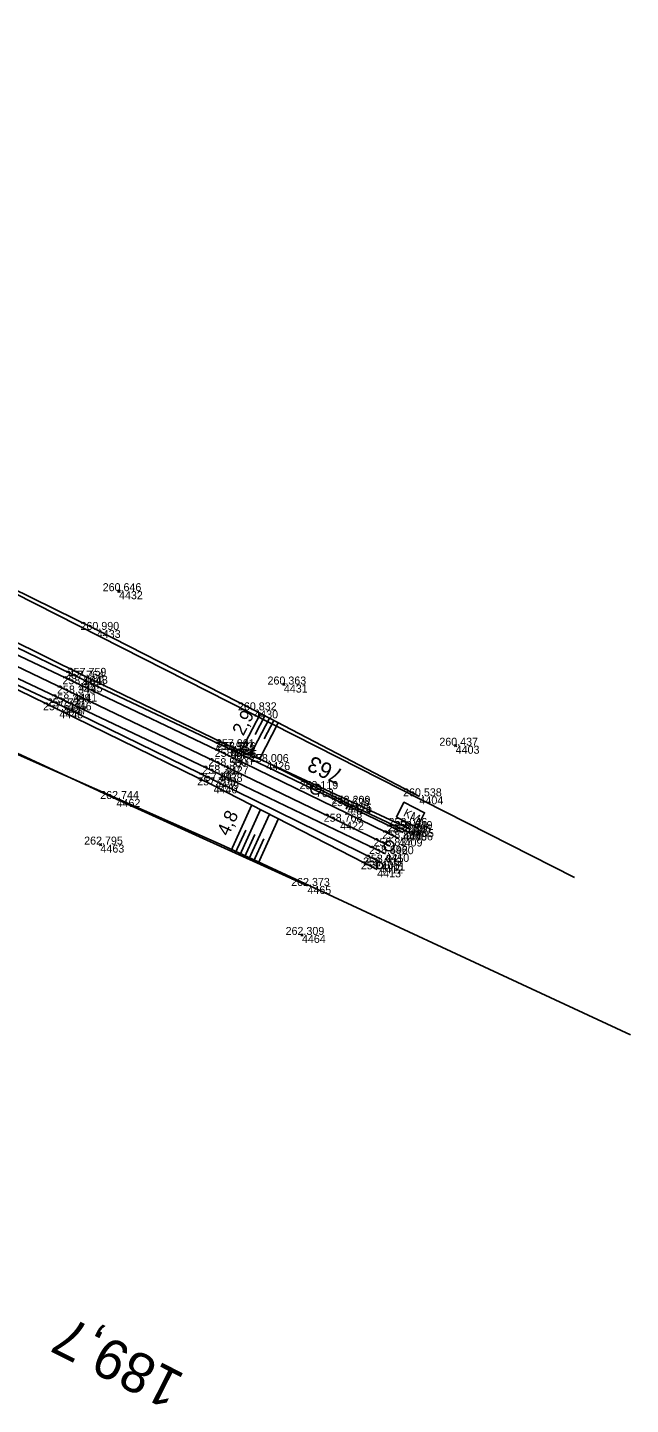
# Model space of a CAD drawing. Extents: x -809970 to -809480, y -1011362 to -1010672.
# Drawn here: x -809570.4 to -809480, y -1011362.4 to -1011155.9 of the extents above; entities that cross this region are included whole.
import ezdxf

# ---------------------------------------------------------------- set-up
doc = ezdxf.new("R2010")
doc.units = 0
for name, color, linetype in [('Vrstva 1', 7, 'Continuous'), ('Vrstva 4', 7, 'Continuous'), ('Vrstva 48', 7, 'Continuous'), ('Vrstva 49', 7, 'Continuous'), ('Vrstva 53', 7, 'Continuous'), ('Vrstva 60', 7, 'Continuous'), ('Vrstva 61', 7, 'Continuous'), ('Vrstva 63', 7, 'Continuous'), ('Vrstva 7', 7, 'Continuous')]:
    doc.layers.add(name, color=color, linetype=linetype)

msp = doc.modelspace()

# ---------------------------------------------------------------- linework, layer by layer
at = {"layer": 'Vrstva 1'}
msp.add_lwpolyline([(-809516.05, -1011278.71), (-809523.51, -1011275.04), (-809540.81, -1011266.71), (-809563.53, -1011255.81), (-809585.84, -1011245.11), (-809604.95, -1011235.93), (-809607.6, -1011234.66), (-809621.68, -1011227.86)], dxfattribs=at)
at = {"layer": 'Vrstva 4'}
for points in [[(-809514.07, -1011276.67), (-809539.83, -1011264.26), (-809562.29, -1011253.6), (-809585.06, -1011242.59), (-809604.03, -1011233.74), (-809622.75, -1011224.34), (-809635.98, -1011217.78), (-809658.04, -1011205.96), (-809678.21, -1011194.44), (-809694.3, -1011183.84), (-809703.86, -1011176.66), (-809724.9, -1011159.78), (-809744.11, -1011141.6), (-809762.15, -1011122.16), (-809774.57, -1011106.33), (-809789.63, -1011085.97), (-809801.28, -1011067.08), (-809811.54, -1011048.02), (-809817.16, -1011036.69), (-809823.08, -1011022.98)], [(-809514.73, -1011277.55), (-809539.87, -1011265.31), (-809562.72, -1011254.42), (-809585.31, -1011243.69), (-809604.51, -1011234.26), (-809623.3, -1011225.16), (-809636.52, -1011218.94), (-809659.57, -1011206.8), (-809678.11, -1011195.78), (-809694.14, -1011185.08), (-809704.56, -1011177.6), (-809725.72, -1011160.53), (-809745.22, -1011142.43), (-809763.07, -1011123.23), (-809775.62, -1011107.42), (-809790.76, -1011086.7), (-809802.43, -1011068.09), (-809812.88, -1011048.59), (-809818.37, -1011037.45), (-809824.5, -1011023.86)], [(-809517.34, -1011281.17), (-809542.25, -1011268.91), (-809565.05, -1011257.74), (-809585.85, -1011248.03), (-809606.19, -1011237.96), (-809624.44, -1011229.46), (-809639.03, -1011221.78), (-809662.37, -1011209.59), (-809679.75, -1011199.24), (-809695.35, -1011189.16), (-809706.37, -1011181.63), (-809728.71, -1011163.52), (-809748.04, -1011145.82), (-809766.46, -1011126.18), (-809779.35, -1011110.29), (-809779.4, -1011110.26), (-809794.33, -1011089.31), (-809806.51, -1011070.34), (-809817.46, -1011050.77), (-809822.78, -1011039.81), (-809827.65, -1011029.26)], [(-809516.72, -1011279.86), (-809541.72, -1011267.84), (-809564.36, -1011257.13), (-809585.64, -1011247.05), (-809605.96, -1011237.21), (-809624.35, -1011228.4), (-809638.66, -1011221.38), (-809661.97, -1011208.93), (-809679.17, -1011198.73), (-809694.94, -1011188.71), (-809705.67, -1011180.87), (-809727.9, -1011162.91), (-809747.29, -1011144.85), (-809765.46, -1011125.12), (-809778.44, -1011109.55), (-809793.36, -1011088.57), (-809805.27, -1011069.6), (-809816.07, -1011050.21), (-809821.49, -1011039.16), (-809826.21, -1011028.82)]]:
    msp.add_lwpolyline(points, dxfattribs=at)
at = {"layer": 'Vrstva 48'}
for p, q in [((-809535.46, -1011258.81), (-809538.4, -1011264.45)), ((-809534.13, -1011259.51), (-809537.02, -1011265.04)), ((-809534.8, -1011259.16), (-809536.25, -1011261.95)), ((-809532.8, -1011260.2), (-809535.63, -1011265.64)), ((-809533.47, -1011259.85), (-809534.9, -1011262.59)), ((-809539.93, -1011279.43), (-809536.78, -1011272.51)), ((-809538.56, -1011280.05), (-809535.44, -1011273.2)), ((-809537.2, -1011280.67), (-809534.11, -1011273.88)), ((-809535.83, -1011281.29), (-809532.77, -1011274.57)), ((-809539.24, -1011279.74), (-809537.68, -1011276.3)), ((-809537.88, -1011280.36), (-809536.33, -1011276.95)), ((-809536.51, -1011280.98), (-809534.97, -1011277.6))]:
    msp.add_line(p, q, dxfattribs=at)
at = {"layer": 'Vrstva 49'}
for p, q in [((-809556.85, -1011240.28), (-809556.5, -1011240.64)), ((-809556.85, -1011240.64), (-809556.5, -1011240.28)), ((-809532.13, -1011254.28), (-809531.77, -1011254.63)), ((-809532.13, -1011254.63), (-809531.77, -1011254.28)), ((-809506.36, -1011263.46), (-809506, -1011263.82)), ((-809506.36, -1011263.82), (-809506, -1011263.46)), ((-809559.63, -1011278.29), (-809559.28, -1011278.64)), ((-809559.63, -1011278.64), (-809559.28, -1011278.29)), ((-809529.41, -1011291.84), (-809529.06, -1011292.19)), ((-809529.41, -1011292.19), (-809529.06, -1011291.84))]:
    msp.add_line(p, q, dxfattribs=at)
for points in [[(-809511.61, -1011271.23), (-809536.39, -1011258.33), (-809560.01, -1011246.27), (-809576.21, -1011238.32), (-809612.21, -1011219.9), (-809615.12, -1011217.12), (-809615.79, -1011215.73), (-809619.54, -1011223.55), (-809624.01, -1011221.32), (-809620.33, -1011213.39), (-809626.47, -1011211.63), (-809636.4, -1011208.19), (-809641.71, -1011205.47), (-809669.15, -1011190.8), (-809699.73, -1011169.4), (-809726.54, -1011146.85), (-809748.5, -1011124.91), (-809769.57, -1011100.55), (-809784.98, -1011078.51), (-809794.37, -1011063.91), (-809798.01, -1011059.09), (-809806.77, -1011045.25), (-809814.25, -1011034.46), (-809820.96, -1011021.87)], [(-809517.95, -1011282.18), (-809542.49, -1011269.58), (-809565.63, -1011258.32), (-809585.98, -1011248.4), (-809606.44, -1011238.24), (-809621.62, -1011231.05), (-809624.45, -1011230.4), (-809627.73, -1011228.86), (-809639.59, -1011222.81), (-809662.84, -1011211.14), (-809680.58, -1011200.68), (-809695.92, -1011190.37), (-809707.33, -1011182.3), (-809729.57, -1011164.32), (-809748.84, -1011146.41), (-809766.98, -1011126.93), (-809779.99, -1011110.78), (-809794.75, -1011089.67), (-809807.08, -1011070.6), (-809818.27, -1011051.22), (-809824.25, -1011040.29), (-809829.11, -1011030.23)], [(-809513.01, -1011276.14), (-809534.58, -1011266.09), (-809539.77, -1011263.86), (-809561.92, -1011253.16), (-809584.64, -1011241.91), (-809603.49, -1011232.88), (-809619.73, -1011225.04), (-809620.87, -1011223.99), (-809623.85, -1011222.57), (-809625.32, -1011222.49), (-809635.81, -1011217.56), (-809657.91, -1011205.7), (-809678.34, -1011193.87), (-809696.27, -1011181.61), (-809696.31, -1011181.59), (-809703.94, -1011175.69), (-809724.27, -1011159.21)], [(-809528.41, -1011284.67), (-809557.05, -1011271.63), (-809578.05, -1011261.94), (-809594.42, -1011254.32), (-809626.26, -1011240.21), (-809627.58, -1011240.01), (-809623.67, -1011231.94), (-809628.13, -1011229.78), (-809632.16, -1011237.96), (-809631.7, -1011238.19), (-809633.92, -1011240.11), (-809638.94, -1011239.66), (-809644.87, -1011236.23), (-809666.21, -1011225), (-809686, -1011209.54), (-809702.86, -1011197.5), (-809722.79, -1011182.74)], [(-809513.17, -1011276.63), (-809522.32, -1011272.35), (-809534.58, -1011266.09)]]:
    msp.add_lwpolyline(points, dxfattribs=at)
at = {"layer": 'Vrstva 53'}
for points in [[(-809817.83, -1011024.91), (-809805.06, -1011048.21), (-809777.13, -1011090.84), (-809773.31, -1011095.41), (-809752.3, -1011120.38), (-809722.41, -1011150.52), (-809685.06, -1011180.11), (-809638.61, -1011207.44), (-809624.45, -1011211.08), (-809620, -1011212.86), (-809615.56, -1011215.28), (-809614.76, -1011215.85), (-809598.39, -1011227.55), (-809488.36, -1011283.38)], [(-809479.96, -1011306.98), (-809541.53, -1011278.39), (-809624.88, -1011241.51), (-809627.72, -1011240.25), (-809632.39, -1011238.49), (-809632.72, -1011238.43), (-809644.97, -1011236.14), (-809685.42, -1011208.04), (-809719.22, -1011184.3), (-809751.99, -1011157.11), (-809779.01, -1011125.97), (-809796.54, -1011101.19), (-809810.89, -1011076.81), (-809836.26, -1011028.53)]]:
    msp.add_lwpolyline(points, dxfattribs=at)
at = {"layer": 'Vrstva 60'}
for p, q in [((-809556.68, -1011240.46), (-809556.68, -1011240.46)), ((-809560.01, -1011246.27), (-809560.01, -1011246.27)), ((-809562.72, -1011254.42), (-809562.72, -1011254.42)), ((-809562.29, -1011253.6), (-809562.29, -1011253.6)), ((-809561.92, -1011253.16), (-809561.92, -1011253.16)), ((-809531.95, -1011254.46), (-809531.95, -1011254.46)), ((-809563.53, -1011255.81), (-809563.53, -1011255.81)), ((-809565.63, -1011258.32), (-809565.63, -1011258.32)), ((-809565.05, -1011257.74), (-809565.05, -1011257.74)), ((-809564.36, -1011257.13), (-809564.36, -1011257.13)), ((-809536.39, -1011258.33), (-809536.39, -1011258.33)), ((-809539.83, -1011264.26), (-809539.83, -1011264.26)), ((-809539.77, -1011263.86), (-809539.77, -1011263.86)), ((-809539.53, -1011264.29), (-809539.53, -1011264.29)), ((-809506.18, -1011263.64), (-809506.18, -1011263.64)), ((-809540.81, -1011266.71), (-809540.81, -1011266.71)), ((-809539.87, -1011265.31), (-809539.87, -1011265.31)), ((-809534.58, -1011266.09), (-809534.58, -1011266.09)), ((-809542.25, -1011268.91), (-809542.25, -1011268.91)), ((-809541.72, -1011267.84), (-809541.72, -1011267.84)), ((-809542.49, -1011269.58), (-809542.49, -1011269.58)), ((-809527.15, -1011270.15), (-809527.15, -1011270.15)), ((-809557.05, -1011271.63), (-809557.05, -1011271.63)), ((-809522.41, -1011272.7), (-809522.41, -1011272.7)), ((-809522.32, -1011272.35), (-809522.32, -1011272.35)), ((-809511.61, -1011271.23), (-809511.61, -1011271.23)), ((-809523.51, -1011275.04), (-809523.51, -1011275.04)), ((-809514.07, -1011276.67), (-809514.07, -1011276.67)), ((-809513.79, -1011275.68), (-809513.79, -1011275.68)), ((-809513.17, -1011276.63), (-809513.17, -1011276.63)), ((-809513.01, -1011276.14), (-809513.01, -1011276.14)), ((-809559.46, -1011278.47), (-809559.46, -1011278.47)), ((-809516.05, -1011278.71), (-809516.05, -1011278.71)), ((-809514.73, -1011277.55), (-809514.73, -1011277.55)), ((-809517.34, -1011281.17), (-809517.34, -1011281.17)), ((-809516.72, -1011279.86), (-809516.72, -1011279.86)), ((-809517.95, -1011282.18), (-809517.95, -1011282.18)), ((-809517.61, -1011281.6), (-809517.61, -1011281.6)), ((-809528.41, -1011284.67), (-809528.41, -1011284.67)), ((-809529.24, -1011292.02), (-809529.24, -1011292.02))]:
    msp.add_line(p, q, dxfattribs=at)
at = {"layer": 'Vrstva 63'}
msp.add_line((-809527.1, -1011270.17), (-809527.19, -1011270.13), dxfattribs=at)
msp.add_circle((-809527.15, -1011270.15), 0.756, dxfattribs=at)
at = {"layer": 'Vrstva 7'}
for p, q in [((-809539.08, -1011264.51), (-809539.98, -1011264.07)), ((-809539.75, -1011264.74), (-809539.31, -1011263.84)), ((-809521.96, -1011272.92), (-809522.86, -1011272.49)), ((-809522.63, -1011273.15), (-809522.19, -1011272.25)), ((-809513.79, -1011275.68), (-809513.51, -1011275.13)), ((-809517.66, -1011281.58), (-809517.57, -1011281.63))]:
    msp.add_line(p, q, dxfattribs=at)
msp.add_lwpolyline([(-809515.07, -1011274.34), (-809513.95, -1011272.12), (-809510.84, -1011273.69), (-809511.95, -1011275.91)], close=True, dxfattribs=at)
for centre, radius in [((-809516.16, -1011278.66), 0.75), ((-809517.61, -1011281.6), 0.5)]:
    msp.add_circle(centre, radius, dxfattribs=at)

# ---------------------------------------------------------------- texts
at = {"layer": 'Vrstva 48'}
for s, rotation, p in [('2,9', 62.9577, (-809538.03, -1011262.27)), ('4,8', 65.5249, (-809540.26, -1011277.31))]:
    msp.add_text(s, height=2, rotation=rotation, dxfattribs=at).set_placement(p)
at = {"layer": 'Vrstva 60'}
for s, p in [('4432', (-809556.68, -1011241.66)), ('4433', (-809560.01, -1011247.47)), ('4445', (-809562.72, -1011255.62)), ('4444', (-809562.29, -1011254.8)), ('4443', (-809561.92, -1011254.35)), ('4431', (-809531.95, -1011255.66)), ('4441', (-809563.53, -1011257.01)), ('4448', (-809565.63, -1011259.52)), ('4447', (-809565.05, -1011258.94)), ('4446', (-809564.36, -1011258.33)), ('4430', (-809536.39, -1011259.53)), ('4436', (-809539.83, -1011265.46)), ('4434', (-809539.77, -1011265.06)), ('4435', (-809539.53, -1011265.49)), ('4403', (-809506.18, -1011264.84)), ('4427', (-809540.81, -1011267.91)), ('4437', (-809539.87, -1011266.51)), ('4426', (-809534.58, -1011267.29)), ('4439', (-809542.25, -1011270.11)), ('4438', (-809541.72, -1011269.05)), ('4440', (-809542.49, -1011270.78)), ('763', (-809527.15, -1011271.35)), ('4462', (-809557.05, -1011272.83)), ('4424', (-809522.41, -1011273.9)), ('4425', (-809522.32, -1011273.55)), ('4404', (-809511.61, -1011272.43)), ('4422', (-809523.51, -1011276.24)), ('4408', (-809514.07, -1011277.87)), ('4407', (-809513.79, -1011276.88)), ('4406', (-809513.17, -1011277.83)), ('4405', (-809513.01, -1011277.34)), ('4463', (-809559.46, -1011279.67)), ('4420', (-809516.05, -1011279.91)), ('4409', (-809514.73, -1011278.75)), ('4411', (-809517.34, -1011282.37)), ('4410', (-809516.72, -1011281.06)), ('4413', (-809517.95, -1011283.38)), ('4412', (-809517.61, -1011282.8)), ('4465', (-809528.41, -1011285.87)), ('4464', (-809529.24, -1011293.22))]:
    msp.add_text(s, height=1.2, dxfattribs=at).set_placement(p)
at = {"layer": 'Vrstva 61'}
for s, p in [('260.646', (-809559.13, -1011240.46)), ('260.990', (-809562.46, -1011246.27)), ('257.764', (-809564.74, -1011253.6)), ('257.759', (-809564.38, -1011253.16)), ('258.164', (-809565.17, -1011254.42)), ('260.363', (-809534.4, -1011254.46)), ('257.727', (-809567.5, -1011257.74)), ('258.208', (-809566.81, -1011257.13)), ('258.343', (-809565.98, -1011255.81)), ('257.614', (-809568.08, -1011258.32)), ('260.832', (-809538.84, -1011258.33)), ('257.901', (-809542.13, -1011263.86)), ('260.437', (-809508.63, -1011263.64)), ('258.374', (-809542.32, -1011265.31)), ('257.923', (-809542.28, -1011264.26)), ('258.516', (-809541.98, -1011264.29)), ('258.387', (-809544.17, -1011267.84)), ('258.580', (-809543.26, -1011266.71)), ('258.006', (-809537.03, -1011266.09)), ('257.705', (-809544.95, -1011269.58)), ('257.897', (-809544.7, -1011268.91)), ('258.119', (-809529.6, -1011270.15)), ('262.744', (-809559.5, -1011271.63)), ('260.538', (-809514.07, -1011271.23)), ('258.626', (-809524.86, -1011272.7)), ('258.209', (-809524.77, -1011272.35)), ('258.768', (-809525.97, -1011275.04)), ('258.046', (-809516.25, -1011275.68)), ('258.049', (-809515.46, -1011276.14)), ('258.807', (-809517.18, -1011277.55)), ('258.255', (-809516.52, -1011276.67)), ('258.225', (-809515.63, -1011276.63)), ('262.795', (-809561.91, -1011278.47)), ('258.596', (-809519.17, -1011279.86)), ('258.837', (-809518.5, -1011278.71)), ('258.108', (-809520.4, -1011282.18)), ('258.609', (-809520.07, -1011281.6)), ('258.075', (-809519.79, -1011281.17)), ('262.373', (-809530.86, -1011284.67)), ('262.309', (-809531.69, -1011292.02))]:
    msp.add_text(s, height=1.2, dxfattribs=at).set_placement(p)
at = {"layer": 'Vrstva 63'}
msp.add_text('763', height=2.4, rotation=154.2598, dxfattribs=at).set_placement((-809522.81, -1011267.41))
at = {"layer": 'Vrstva 7'}
for s, height, rotation, p in [('KM', 1.247, 333.2876, (-809514.14, -1011274.12)), ('189,7', 6, 153.2876, (-809546.58, -1011358.02))]:
    msp.add_text(s, height=height, rotation=rotation, dxfattribs=at).set_placement(p)

doc.saveas('drawing.dxf')
